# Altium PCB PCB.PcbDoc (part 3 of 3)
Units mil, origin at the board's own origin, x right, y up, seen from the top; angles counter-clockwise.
Board outline 5645.41 x 3720.47 mil, 4 copper layers (Top Layer, Signal Layer 1, Signal Layer 2, Bottom Layer), stack 61.2 mil thick; 253 components, 113 nets, 631 pads, 211 vias.
Unrouted connection lines stored in the file: 1.
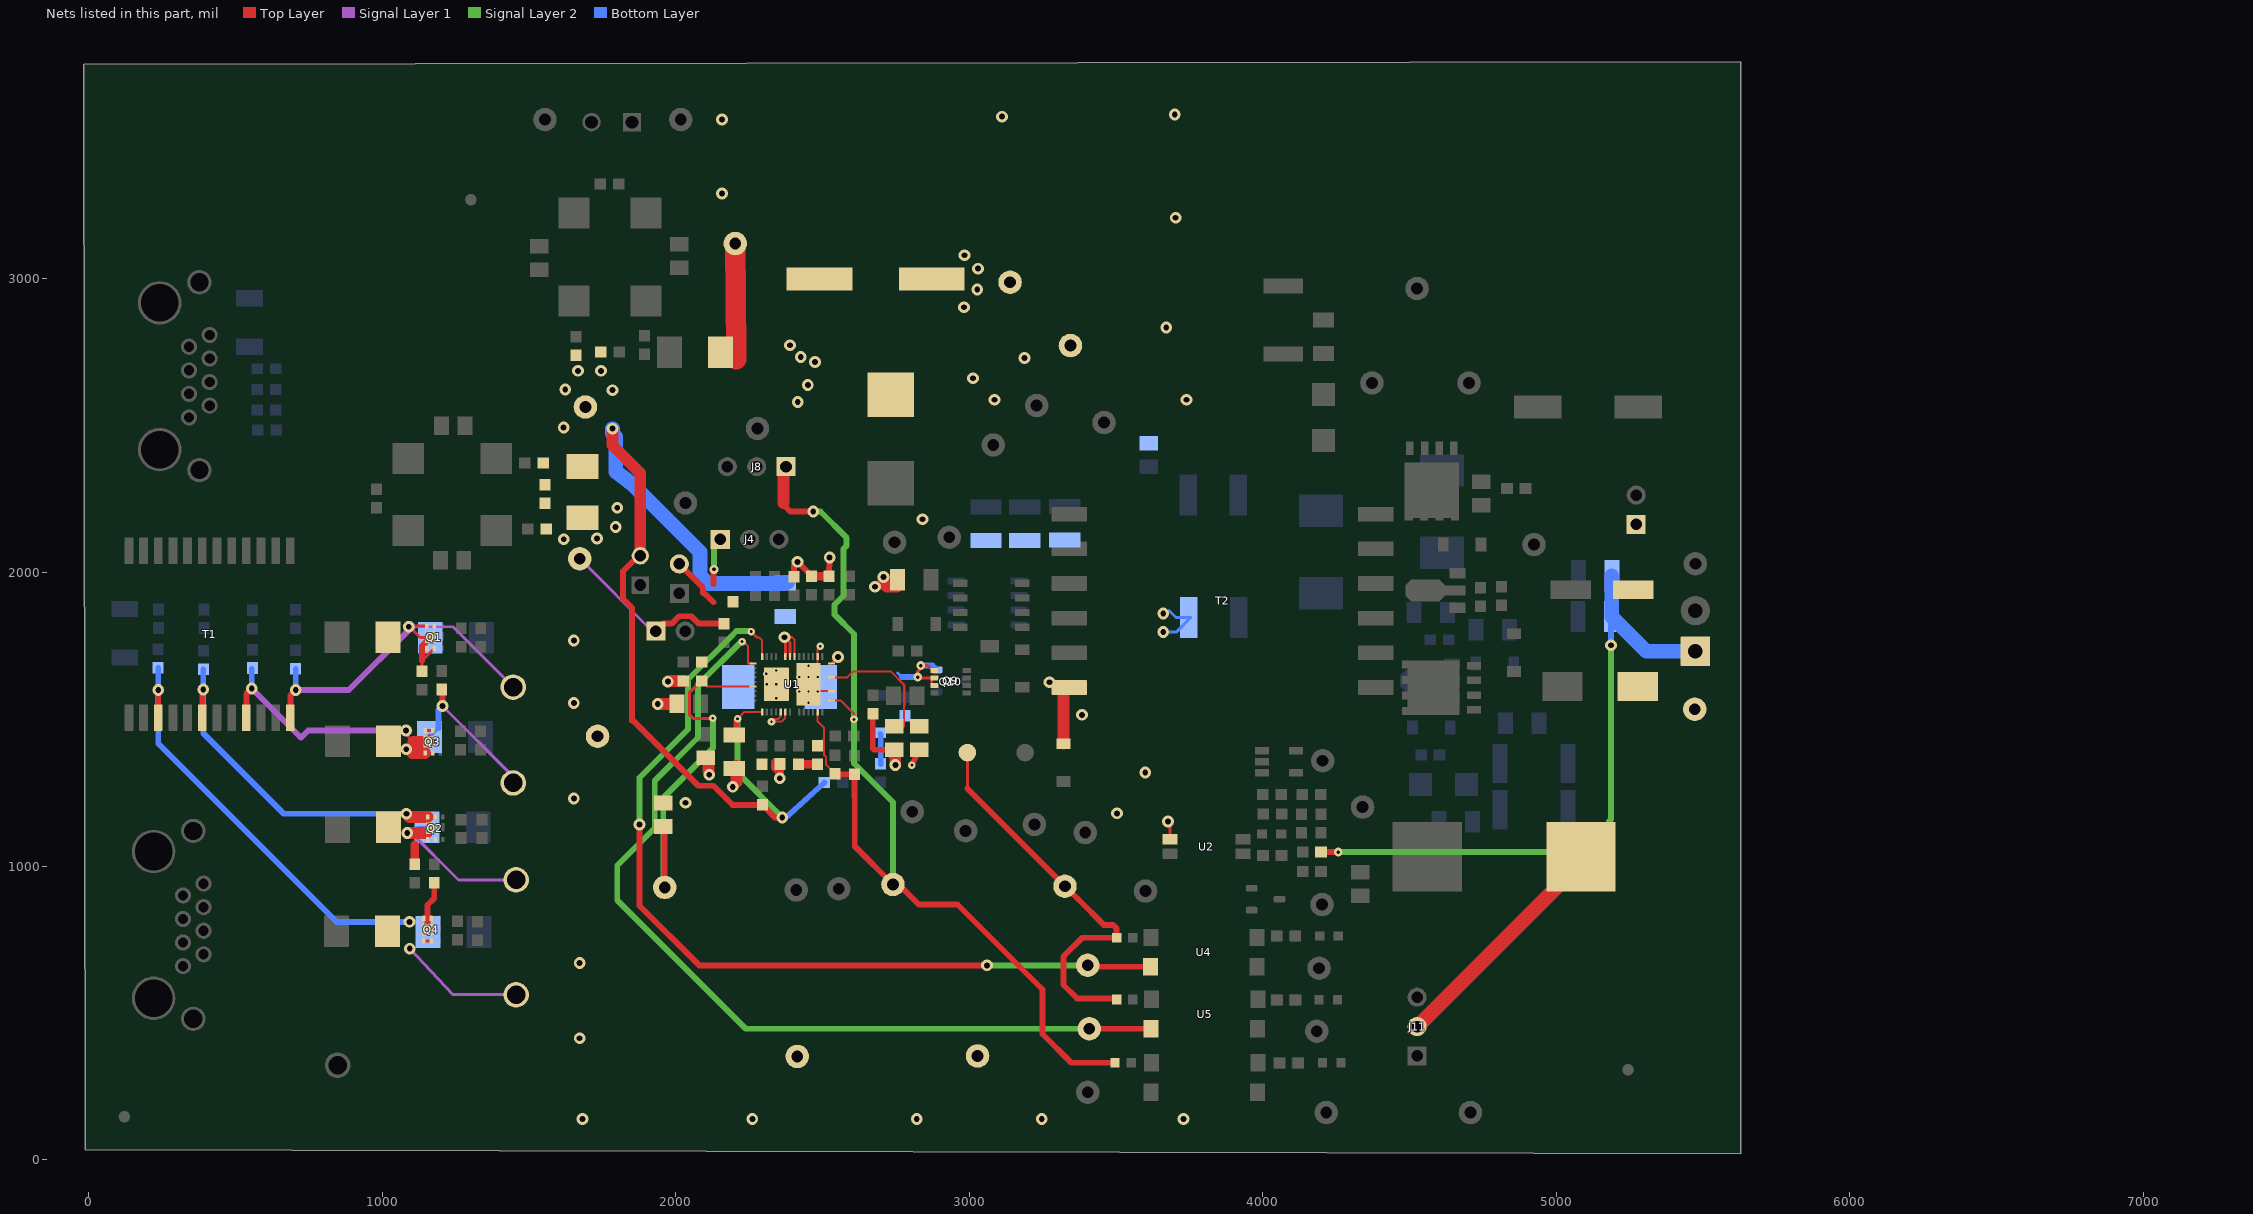
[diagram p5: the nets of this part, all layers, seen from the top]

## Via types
v1: diameter 40, hole 20, Top Layer to Bottom Layer, 113 vias
v2: diameter 40, hole 20, Top Layer to Bottom Layer, tented both sides, 29 vias
v3: diameter 40, hole 20, Top Layer to Bottom Layer, tented top, 15 vias
v4: diameter 19.68, hole 7.87, Top Layer to Bottom Layer, 13 vias
v5: diameter 26, hole 10, Top Layer to Bottom Layer, tented both sides, 11 vias
v6: diameter 40, hole 20, Top Layer to Bottom Layer, tented bottom, 10 vias
v7: diameter 30, hole 12, Top Layer to Bottom Layer, tented both sides, 6 vias
v8: diameter 30, hole 12, Top Layer to Bottom Layer, tented top, 5 vias
v9: diameter 26, hole 10, Top Layer to Bottom Layer, tented top, 3 vias
v10: diameter 26, hole 8, Top Layer to Bottom Layer, tented both sides, 2 vias
v11: diameter 20, hole 8, Top Layer to Bottom Layer, 1 vias
v12: diameter 26, hole 8, Top Layer to Bottom Layer, tented bottom, 1 vias
v13: diameter 26, hole 10, Top Layer to Bottom Layer, 1 vias
v14: diameter 30, hole 12, Top Layer to Bottom Layer, 1 vias

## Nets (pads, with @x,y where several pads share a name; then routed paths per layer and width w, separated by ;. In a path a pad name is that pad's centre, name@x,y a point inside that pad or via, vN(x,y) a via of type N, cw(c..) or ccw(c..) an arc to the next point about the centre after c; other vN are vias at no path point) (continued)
PGND: C8.2 C16.2 C20.2 C21.2 C22.2 C23.2 C24.2 C25.2 C32.2 C35.1 C38.2 C40.1 C41.2 C42.1 C46.2 D16.2 D20.1 D24.1 J4.1 J9.2 L3.2 Q9.2 Q10.1 Q10.2 Q10.3 R11.1 R26.1 R36.1 R37.1 R52.1 R54.1 R55.1 T2.6 TP29.1 TP35.1 TP39.1 TP42.1 U1.2 U1.7 U1.8 U1.9 U1.39 U1.45 U1.46 U2.3 | length 2558.2
  Top Layer w7: v3(2371.38,1779.4) 2396.36,1779.4 2405.4,1770.36 U1.7@2405.4,1713.66 ; U1.46@2476.27,1595.55 U1.39@2531.39,1595.55 ; U1.46@2484.14,1650.67 U1.2@2484.14,1713.66 2484.14,1739.8 v5(2493.02,1748.67) ; U1.45@2531.39,1690.04 v2(2553.37,1712.03)
  Top Layer w10: L3.2@1661.01,2740.76 L3.2@1667.86,2733.91 ; C8.2@1735.94,2740.76 C8.2@1745.79,2750.6 ; R54.1@2290.49,1332.27 2303.07,1344.85 R54.1@2302.39,1345.53 ; v3(2371.38,1779.4) v3@2373.91,1776.87 ; U1.9@2373.91,1713.66 v3@2373.91,1776.87 ; U1.8@2389.65,1713.66 2389.65,1761.12 v3@2373.91,1776.87 ; C35.1@2419.04,1346.41 C35.1@2419.45,1346.82 ; C41.2@2463.64,1987.19 C41.2@2463.64,1988.09 ; U1.46@2476.27,1595.55 U1.46@2452.65,1619.18 U1.46@2484.14,1650.67 ; C38.2@2725.55,1377.34 C38.2@2744.29,1396.08 C38.2@2744.29,1378.11 ; v7@2813.8,1640.83 v7@2829.48,1640.83 ; v7(2824.8,1643.7) v7@2824.8,1645.51 ; 2872.9,1630.99 2872.9,1617.47 Q10.3@2875.13,1615.24 ; Q10.1@2875.13,1666.42 2858.48,1683.07 v7(2835.66,1683.07) 2835.66,1674.03 2824.8,1663.16 v7@2824.8,1645.51 ; Q10.2@2881.89,1640.83 v7@2829.48,1640.83 ; T2.6@3318.26,1593.23 T2.6@3321.99,1589.5 ; v1(3677.55,1151.57) 3684.55,1144.58 U2.3@3684.55,1091.15 ; v7@2824.8,1645.51 v7@2829.48,1640.83
  Top Layer w20: J9.2@2012.89,2029.13 2092.52,1949.5 2092.52,1929.93 2096.93,1929.93 2102.99,1923.87 2103.66,1923.87 2129.1,1898.44 ; 2129.1,1961.43 2129.1,2008.52 v8(2130.92,2010.34) ; R37.1@2403.18,1985.08 2403.18,2023.88 v3(2415.51,2036.22) C41.2@2463.64,1988.09 ; C46.2@2523.35,1987.19 v3(2524.98,2051.39) v3@2524.98,2042.68 ; C42.1@2671.97,1518.37 2671.97,1401.09 2676.98,1396.08 C38.2@2744.29,1396.08 ; v5(2805.12,1343.46) C32.2@2830.91,1396.08
  Top Layer w30: R55.1@2340.44,1353.85 2340.44,1335.72 2354.97,1321.2 v2(2354.97,1299.21) ; C35.1@2419.45,1346.82 C40.1@2482.83,1346.82 ; C41.2@2463.64,1987.19 C46.2@2523.35,1987.19
  Top Layer w40: v3(2708.13,1984.44) 2708.13,1962.24 2719.32,1951.05 R52.1@2754.13,1951.05 ; C38.2@2744.29,1378.11 2748.71,1373.69 v2(2748.71,1344.07) ; D16.2@3321.99,1416.94 T2.6@3321.99,1589.5
  Signal Layer 2 w20: v8(2130.92,2010.34) 2130.92,2091.51 J4.1@2152.24,2112.84 J4.1@2151.5,2109.55
  Bottom Layer w10: D20.1@2693.4,1453.34 D20.1@2698.84,1447.89 ; 2756.74,1657.54 2770.58,1643.7 ; v1(3661.42,1797.38) 3706.1,1797.38 3707.18,1798.46 3755.31,1846.6 3704.95,1846.6 3680.71,1870.83 3670.12,1860.24 v1(3661.66,1860.24)
  Bottom Layer w20: R26.1@2698.84,1347.81 D20.1@2698.84,1447.89 ; 2770.58,1643.7 v7(2824.8,1643.7) ; v7(2835.66,1683.07) 2875.14,1683.07 Q9.2@2889.82,1668.39
  other v1: 1683.07,137.8 2261.56,137.8 2821.68,137.8 3247.51,137.8 3730.31,137.8 1673.23,413.39 1673.23,669.29 3600.14,1318.9 3384.99,1514.94 3273.86,1625.99 2841.22,2181.56 3740.46,2588.58 3013.69,2662.02 3188.98,2730.49 3671.86,2834.65 2982.28,2903.54 3027.62,2964.28 3030.49,3035.15 2984.05,3080.71 3703.86,3208.66 2158.54,3543.31 3112.49,3553.15 3700.79,3560.78
  other v2: 3086.46,2588.58 1667.86,2687.01 1745.79,2687.01 2158.54,3291.03
  other v3: 3503.94,1179.47
  other v4: 2452.65,1556.18 2420.95,1594.57 2452.65,1594.57 2484.34,1594.57 2420.95,1643.78 2452.65,1643.78 2484.34,1643.78 2452.65,1682.17
  other v6: 2679.76,1951.59
PPD: C11.1 R14.2 R19.2 TP10.1 U1.19 | length 1261.6
  Top Layer w7: R19.2@2089.03,1630.93 2108.66,1611.3 U1.19@2263.67,1611.3
  Top Layer w10: C11.1@1958.66,1134.89 C11.1@1962.89,1130.66 ; R19.2@2089.03,1630.93 2087.4,1630.93 2046.87,1590.41 2046.87,1516.74 2060.6,1503.02 v10(2127.09,1503.02)
  Top Layer w20: TP10.1@1962.89,927.16 C11.1@1962.89,1130.66
  Signal Layer 2 w20: TP10.1@1958.18,922.18 1958.18,1232.71 2127.09,1401.62 v10(2127.09,1503.02)
PR12: C1.2 D2.2 D7.1 Q1.1 Q1.2 Q1.5 Q1.6 Q1.8 R16.2 T1.24 TP1.1 | length 1490.4
  Top Layer w10: R16.2@1136.5,1663.89 1136.5,1699.47 Q1.2@1177.83,1740.81 ; 1136.5,1750.65 1142.4,1750.65 Q1.1@1152.24,1740.81 ; Q1.6@1152.24,1817.58 1104.76,1817.58 1102.37,1815.19 v2(1090.81,1815.19) 1093.38,1815.19 1129.37,1779.2 Q1.8@1165.04,1779.2
  Top Layer w20: T1.24@687.6,1504.68 687.6,1581.12 v1(705.84,1599.36) ; 1136.5,1699.47 1136.5,1750.65 Q1.8@1165.04,1779.2
  Signal Layer 1 w10: v2(1090.81,1815.19) 1241.2,1815.19 1245.69,1810.69 TP1.1@1446.85,1609.54
  Signal Layer 1 w20: v1(705.84,1599.36) 886.54,1599.36 1090.81,1803.63 v2(1090.81,1815.19)
  Bottom Layer w10: C1.2@705.58,1672.06 C1.2@705.84,1671.79 ; D7.1@1130.72,1777.85 D7.1@1164.14,1777.85
  Bottom Layer w20: v1(705.84,1599.36) C1.2@705.84,1671.79
  Bottom Layer w40: v2(1090.81,1815.19) v2@1093.38,1815.19
PR36: C2.2 D3.2 D8.1 Q3.1 Q3.2 Q3.5 Q3.6 Q3.8 R15.2 T1.21 TP2.1 | length 1572.9
  Top Layer w10: v6(1081.95,1461.51) 1081.95,1448.01 1106.64,1423.32 ; v6(1082.55,1397.64) 1090.61,1397.64 1103.31,1384.93 ; Q3.1@1147.12,1384.93 Q3.2@1172.71,1384.93 ; Q3.6@1147.12,1461.71 Q3.5@1172.71,1461.71 ; Q3.8@1159.92,1423.32 1159.92,1445.85 ; R15.2@1203.42,1601.45 R15.2@1205.82,1599.05
  Top Layer w20: T1.21@537.6,1504.68 537.6,1586.55 v1(556.1,1605.05) ; v2(1205.82,1545.28) R15.2@1205.82,1599.05
  Top Layer w40: 1103.31,1384.93 Q3.1@1147.12,1384.93 ; 1106.64,1423.32 Q3.8@1159.92,1423.32
  Signal Layer 1 w10: v2(1205.82,1545.28) 1446.85,1304.25 TP2.1@1446.85,1283.01
  Signal Layer 1 w20: v1(556.1,1605.05) 724.15,1437.01 748.65,1461.51 v6(1081.95,1461.51)
  Bottom Layer w10: C2.2@556.1,1671.61 C2.2@559.05,1674.56 ; D8.1@1162.14,1439.37 D8.1@1192.36,1469.59
  Bottom Layer w20: v1(556.1,1605.05) C2.2@556.1,1671.61 ; D8.1@1192.36,1469.59 1192.36,1531.81 v2(1205.82,1545.28)
PR45: C3.2 D4.2 D9.1 Q2.1 Q2.2 Q2.5 Q2.6 Q2.8 R18.2 T1.18 TP3.1 | length 1828.1
  Top Layer w10: v1@387.6,1598.17 v1(390.88,1601.45) ; v6(1082.68,1178) v6@1093.46,1167.22 ; Q2.8@1151.22,1112.2 Q2.8@1167.84,1128.83
  Top Layer w20: T1.18@387.6,1504.68 v1@387.6,1598.17
  Top Layer w30: R18.2@1111.38,1005.91 1111.38,1072.37
  Top Layer w40: v6(1086,1112.2) Q2.8@1151.22,1112.2 ; v6@1093.46,1167.22 Q2.6@1155.04,1167.22
  Signal Layer 1 w10: v6(1086,1112.2) 1091.84,1112.2 1096.37,1116.74 1260.36,952.76 TP3.1@1456.69,952.76
  Bottom Layer w10: C3.2@390.88,1669.79 C3.2@391.73,1670.64 ; D9.1@1120.49,1131.78 D9.1@1153.67,1131.78
  Bottom Layer w20: C3.2@390.88,1669.79 v1(390.88,1601.45) 390.88,1452.06 664.94,1178 v6(1082.68,1178)
PR78: C4.2 D5.2 D10.1 Q4.1 Q4.2 Q4.5 Q4.6 Q4.8 R17.2 T1.15 TP4.1 | length 2139.8
  Top Layer w10: v6(1094.4,718.5) v6@1094.4,725.68 ; Q4.1@1141.73,744.93 Q4.2@1167.32,744.93 ; Q4.6@1141.73,821.7 1154.53,821.7 Q4.5@1167.32,821.7
  Top Layer w20: T1.15@237.6,1504.68 v1(237.6,1599.36) ; Q4.8@1154.53,783.32 1154.53,821.7 1154.53,867.02 1177.83,890.33 R17.2@1177.83,943.74
  Signal Layer 1 w10: v6@1091.48,711.94 v6@1094.4,709.03 ; v6@1094.4,723.51 v6@1094.4,709.03 ; TP4.1@1437.01,562.69 1240.73,562.69 v6(1094.4,718.5) v6@1094.4,709.03
  Bottom Layer w10: C4.2@236.43,1675.6 C4.2@237.6,1674.43 ; v6@1086.15,806.96 1088.87,809.68 v6(1093.35,809.68) 1089.62,809.68 v6@1089.25,810.05
  Bottom Layer w20: C4.2@237.6,1674.43 v1(237.6,1599.36) 237.6,1417.66 844.83,810.43 845.57,809.68 v6(1093.35,809.68)
TPH: TP44.1 U1.13 U4.2 | length 3055.7
  Top Layer w7: v5(2257.76,1798.46) 2277.58,1778.65 2285.09,1778.65 2295.17,1768.57 U1.13@2295.17,1713.66
  Top Layer w10: TP44.1@3404.21,661.49 TP44.1@3409.01,656.69
  Top Layer w20: v1(1877.39,1141.73) 1877.39,864.74 2080.64,661.49 v1(3061.02,661.49) ; TP44.1@3409.01,656.69 U4.2@3618.54,656.69
  Signal Layer 2 w10: v1(3061.02,661.49) v1@3073.47,661.49
  Signal Layer 2 w20: v1(1877.39,1141.73) 1877.39,1300.55 2042.67,1465.84 2042.67,1635.72 2187.53,1780.57 2207.52,1800.55 2255.67,1800.55 v5(2257.76,1798.46) ; v1@3073.47,661.49 TP44.1@3404.21,661.49
TPL: TP46.1 U1.14 U5.2 | length 3162.9
  Top Layer w7: v5(2226.83,1764.44) 2231.61,1764.44 2246.08,1749.97 2246.08,1690.04 U1.14@2263.67,1690.04
  Top Layer w20: TP46.1@3409.85,445.54 U5.2@3620.53,445.54
  Signal Layer 2 w20: v5(2226.83,1764.44) 2223.34,1764.44 2076.77,1617.88 2076.77,1438.14 1929.13,1290.5 1929.13,1129.43 1801.18,1001.47 1801.18,883.32 2238.96,445.54 TP46.1@3409.85,445.54
VB: C40.2 J8.1 R43.2 R46.2 R64.2 TP33.1 U1.34 U1.37 | length 3644.7
  Top Layer w7: C40.2@2482.83,1409.81 2505.64,1432.62 ; U1.34@2484.14,1524.69 2484.14,1492.23 2505.64,1470.73 2505.64,1432.62 ; U1.37@2531.39,1564.06 2562.84,1564.06 2607.96,1518.93 v13(2607.96,1499.75) ; R46.2@2543.68,1314.08 2512.91,1344.85 2512.91,1371.21 2505.64,1378.48 2505.64,1432.62
  Top Layer w10: 2361.56,2236.51 2367.51,2236.51 ; C40.2@2480.31,1409.81 C40.2@2482.83,1409.81 ; R46.2@2543.68,1314.08 R46.2@2545.19,1312.57
  Top Layer w20: 2361.56,2236.51 2390.55,2207.52 ; 2390.57,2207.54 v3(2469.13,2207.54) ; R46.2@2545.19,1312.57 R43.2@2610.05,1312.57 2610.55,1150.17 2610.55,1067.22 TP33.1@2740.65,937.12 ; TP33.1@2750.43,946.9 2828.65,868.68 2960.63,868.68 3250.12,579.18 3250.12,428.01 3348.57,329.56 R64.2@3497.5,329.56
  Top Layer w40: 2367.51,2236.51 J8.1@2367.51,2352.03
  Signal Layer 2 w20: v3(2469.13,2207.54) 2493.46,2207.54 2582.85,2118.15 2582.85,2091.57 2572.22,2080.94 2572.22,1920.62 2541.35,1889.75 2541.35,1864.17 2542.05,1863.47 2542.05,1856.23 2607.96,1790.32 v13(2607.96,1499.75) 2607.96,1349.8 2740.65,1217.11 TP33.1@2740.65,937.12
VCC: C32.1 C38.1 L9.1 R62.2 R63.2 TP24.1 U1.42 | length 1815.6
  Top Layer w7: U1.42@2531.39,1642.8 2584.93,1642.8 2605.22,1663.1 2732.8,1663.1 2779.05,1616.85 2779.05,1544.42 2778.35,1543.72 2778.35,1476.08 C38.1@2744.29,1476.08
  Top Layer w10: 2994.22,1264.39 L9.1@2994.22,1386.08
  Top Layer w20: 2994.22,1264.39 3301.39,956.51 TP24.1@3326.77,931.13 3370.79,887.29 3458.82,799.61 3490.23,799.61 3502.84,787 R62.2@3502.84,755.76 3385.52,755.76 3321.99,692.24 3321.99,594.7 3368.06,548.63 3499.75,548.63 R63.2@3502.84,545.54
VDD: C10.1 C20.1 C21.1 C34.1 D1.1 D6.1 J5.2 L4.2 L7.1 R25.2 R51.1 TP9.1 TP13.1 U1.23 | length 3873.4
  Top Layer w7: v5@2207.45,1497.86 v5(2211.35,1501.77) 2234.27,1524.69 U1.23@2295.17,1524.69
  Top Layer w10: D1.1@2153.79,2750.6 2203.42,2800.24
  Top Layer w20: J5.2@1879.92,2063.29 1820.77,2004.13 1820.77,1910.19 1852.05,1878.91 1852.05,1494.7 1856.24,1494.7 2077.68,1273.26 2128.91,1273.26 2193.91,1208.26 R51.1@2296.06,1208.26 2337.8,1166.52 2337.8,1165.19 v3(2363.61,1165.19) ; C34.1@2207.45,1444.73 v5@2207.45,1497.86 ; R51.1@2296.06,1211.7 R51.1@2296.06,1208.26
  Top Layer w40: v1(1785.09,2490.16) 1785.09,2433.53 1879.92,2338.71 J5.2@1879.92,2063.29
  Top Layer w70: TP9.1@2203.42,3120.73 2206.35,2751.02 2206.54,2726.38
  Signal Layer 2 w20: v5(2211.35,1501.77) 2211.35,1317.45 v3(2363.61,1165.19)
  Bottom Layer w20: v3@2369.01,1159.25 R25.2@2507.02,1284.56
  Bottom Layer w50: v1(1785.09,2490.16) 1785.09,2474.12 1796.53,2462.68 1796.53,2344.3 1854.06,2299.57 2017.21,2135.83 2083.04,2070 2083.04,1990.51 2111.09,1962.46 2370.91,1962.46 2374.77,1966.32 2381.44,1966.34 2374.77,1966.42 C20.1@2373.93,1966.43
  other v1: 1618.73,2493.77 2416.32,2580.74 1624.02,2623.29 2450.79,2638.62 2475.09,2717.39 2389.77,2774.34
  other v2: 1785.47,2621.34 2426.29,2733.91
VOUT: C27.2 C28.1 C29.2 J6.1 J7.1 J11.2 L8.2 R39.2 TP14.1 | length 3029.2
  Top Layer w10: L8.2@5085.08,1011.88 L8.2@5085.08,1032.05
  Top Layer w20: R39.2@4199.07,1047.45 v7(4257.43,1047.45)
  Top Layer w50: J11.2@4526.26,453.06 L8.2@5085.08,1011.88
  Signal Layer 2 w20: v7(4257.43,1047.45) 5094.82,1047.45 5189.1,1141.73 5179.25,1151.57 5187,1159.32 v2(5187,1751.97)
  Bottom Layer w10: C29.2@5187,1847.86 C29.2@5189.1,1849.96
  Bottom Layer w20: v2(5187,1751.97) C29.2@5187,1847.86
  Bottom Layer w50: C27.2@5189.1,1988.9 C29.2@5189.1,1849.96 5307.09,1731.97 J6.1@5474.53,1731.97
VSS: C10.2 C11.2 C34.2 D6.2 D24.2 J10.1 L6.2 R19.1 R40.1 R47.1 R49.1 TP11.1 TP38.1 U1.27 U1.28 U1.47 | length 980.2
  Top Layer w7: v12(2326.77,1491.14) v12@2333.84,1491.14 ; U1.27@2359.22,1524.69 2357.72,1523.19 2357.72,1509.32 2349.91,1501.5 2334.86,1501.5 2334.86,1491.85 v12@2334.71,1491.69 ; U1.28@2372.84,1524.69 2372.84,1503.38 2361.31,1491.85 2340.12,1491.85 2337.33,1489.07 v12@2334.71,1491.69 ; v12@2333.84,1491.14 2334.15,1491.14 v12@2334.71,1491.69 ; v12@2333.84,1491.14 2334.55,1491.85 v12@2334.71,1491.69
  Top Layer w10: v2(1973.68,1628.05) v2@1975.62,1629.98 ; v3@2112.1,1324.39 2114.61,1321.87 v3(2114.61,1311.13) ; v2(2194.88,1269.68) 2201.94,1269.68 v2@2207.95,1275.69
  Top Layer w20: J10.1@1932.68,1800.55 1957.77,1825.64 1986.55,1825.64 2011.82,1850.91 2053.54,1850.91 2078.81,1825.64 R40.1@2165.79,1825.64
  Top Layer w40: v1(1939.22,1552.39) 1979.95,1552.39 R49.1@1982.38,1554.82 ; v2@1975.62,1629.98 R19.1@2026.88,1629.98 ; v3@2112.1,1324.39 R47.1@2112.1,1368.37 ; 2207.45,1286.02 C34.2@2207.45,1340.38
  Signal Layer 1 w10: TP11.1@1673.23,2047.24 1919.92,1800.55 J10.1@1932.68,1800.55
  other v1: 2033.74,1215.5 1653.54,1230.32 1653.54,1555.55 1653.54,1768.57 1618.98,2113.16 1732.28,2116.14 1795.98,2155.02 1801.18,2220.73
  other v4: 2343.39,1571.93 2310.91,1619.18 2343.39,1619.18 2375.88,1619.18 2343.39,1666.42
  other v11: 2308.68,1654.51
pads on no net: FID1.1 FID2.1 FID3.1 H1.0 H2.0 H3.0 H4.0 LBL1.0 Q1.0 Q2.0 Q3.0 Q4.0 Q8.9@4521.67,2259.01 Q8.9@4521.67,2329.09 Q8.9@4578.76,2259.01 Q8.9@4578.76,2292.47 Q8.9@4578.76,2329.09 Q8.9@4635.84,2259.01 Q8.9@4635.84,2329.09 SH-J1.0 SH-J2.0 SH-J3.0 SH-J4.0 SH-J5.0 SH-J6.0 SH-J7.0 U1.6 U1.10 U1.15 U1.16 U1.22 U1.25 U1.26 U1.29 U1.30 U1.36 U1.44 U3.1 U3.2
copper on no net: | length 159.4
  Top Layer w7: 2288.74,1464.69 2368.03,1464.69 2374.8,1471.46 2421.15,1524.69

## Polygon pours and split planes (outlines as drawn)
VSS on Bottom Layer "BOTTOM_LAYER_VSS_P006" (solid, remove dead copper, pour order 6): 1599.53,2254.44 1599.53,1188.74 2245.32,1188.74 2245.32,1374.46 2380.4,1509.55 2380.4,1719.41 2377.64,1722.17 2117.51,1722.17 2117.51,1849.85 1829.39,1849.85 1829.39,2249.31 1824.77,2253.94 1594.49,2253.94
PGND on Bottom Layer "BOTTOM_LAYER_PGND_P030" (solid, remove dead copper, pour order 30): 2084.75,3641.73 2091.34,3635.13 2091.35,2764.49 3779.53,2764.49 3779.53,3641.73 2091.34,3641.73
PGND on Bottom Layer "BOTTOM_LAYER_PGND_P024" (solid, remove dead copper, pour order 24): 1601.07,2772.25 1601.07,59.76 3778.82,59.76 3779.53,59.06 3779.53,2772.25
GND on Bottom Layer "BOTTOM_LAYER_GND_P017" (solid, remove dead copper, pour order 17): 3882.29,3641.73 3882.29,67.04 5569.75,67.04 5559.53,77.26 5559.53,3641.73
EARTH on Bottom Layer "BOTTOM_LAYER_EARTH_P016" (solid, remove dead copper, pour order 16): 19.68,255.13 34.02,3120.08 1227.16,3120.08 1231.97,3115.27 1231.97,1960.53 1326.37,1960.53 1383.26,1903.64 1383.26,1684.85 1519.17,1684.85 1530.51,1673.51 1530.51,47.58 19.68,53.86
EARTH on Bottom Layer "BOTTOM_LAYER_EARTH_P013" (solid, remove dead copper, pour order 13): 1227.16,618.95 1325.7,618.95 1387.8,681.04 1387.8,1668.59 1522.13,1668.59 1535.43,1681.9 1535.43,58.34 1227.16,58.34 1217.16,68.34 1217.16,619.92
no net on Bottom Layer "BOTTOM_LAYER_NONET_P009" (solid, remove dead copper, pour order 9): 108.96,2754.48
VSS on Top Layer "TOP_LAYER_VSS_P007" (solid, remove dead copper, pour order 7): 1537.94,2244.22 1547.42,2234.74 1547.42,2118.15 1589.54,2118.15 1603.22,2104.48 1603.22,1186.64 2246.69,1186.64 2246.69,1457.24 2331.52,1457.24 2387.27,1512.99 2387.27,1717.31 2140.51,1717.31 2117.93,1739.89 2117.93,1860.59 1834.91,1860.59 1832.07,1857.75 1829.46,1860.36 1829.46,2251.8 1551.23,2251.8 1550.2,2250.77
no net on Top Layer "TOP_LAYER_NONET_P032" (solid, remove dead copper, pour order 32): 1604.57,2234.25 1611.07,2227.75 1611.07,1199.4
no net on Top Layer "TOP_LAYER_NONET_P031" (solid, remove dead copper, pour order 31): 935.56,1241.94
PGND on Top Layer "TOP_LAYER_PGND_P027" (solid, remove dead copper, pour order 27): 2091.34,3641.73 2098.96,2401.8 3779.53,2401.8 3779.53,3641.73
PGND on Top Layer "TOP_LAYER_PGND_P025" (solid, remove dead copper, pour order 25): 1604.57,2774.34 1604.57,50.5 3778.24,50.5 3779.53,49.21 3779.53,2774.34
VSS on Top Layer "TOP_LAYER_VSS_P022" (solid, remove dead copper, pour order 22): 1535.79,2246.32 1545.28,2236.84 1545.28,2120.25 1587.4,2120.25 1601.07,2106.58 1601.07,1188.74 2244.54,1188.74 2244.54,1459.34 2329.37,1459.34 2385.13,1515.09 2385.13,1719.41 2138.36,1719.41 2115.79,1741.99 2115.79,1862.69 1832.76,1862.69 1829.92,1859.85 1827.31,1862.46 1827.31,2253.9 1549.08,2253.9 1548.05,2252.87
GND on Top Layer "TOP_LAYER_GND_P020" (solid, remove dead copper, pour order 20): 3877.95,1830.27 3877.95,67.04 5561.02,67.04 5561.02,868.68 4423.55,868.68 4397.39,894.84 4397.39,1712.37 4279.48,1830.27
GND on Top Layer "TOP_LAYER_GND_P019" (solid, remove dead copper, pour order 19): 3877.95,3640.32 3877.95,1830.27 5561.02,1830.27 5561.02,3640.32
EARTH on Top Layer "TOP_LAYER_EARTH_P015" (solid, remove dead copper, pour order 15): 29.53,3120.08 1227.16,3120.08 1227.16,1955.16 1223.11,1951.11 1245.43,1928.79 1340.53,1928.79 1340.53,1715.86 1366.12,1690.26 1535.43,1690.26 1535.43,62.65 1526.48,53.7 22.04,53.7 22.04,3112.59
no net on Top Layer "TOP_LAYER_NONET_P011" (solid, remove dead copper, pour order 11): 1241.31,2849.25
no net on Top Layer "TOP_LAYER_NONET_P010" (solid, remove dead copper, pour order 10): 1238.86,2362.2
VSS on Signal Layer 2 "SIGNAL_LAYER_2_VSS_P005" (solid, remove dead copper, pour order 5): 1599.53,2251.82 1599.53,1190.29 1601.07,1188.74 2253.9,1188.74 2253.9,1371.11 2247.93,1377.08 2386.2,1515.35 2386.2,1713.61 2380.4,1719.41 2134.94,1719.41 2134.94,1852.86 2131.93,1849.85 1829.39,1849.85 1829.39,2251.82
PGND on Signal Layer 2 "SIGNAL_LAYER_2_PGND_P029" (solid, remove dead copper, pour order 29): 2096.46,3639.42 2096.46,2509.34 3776.02,2509.34 3779.37,2505.99 3779.53,3639.42
PGND on Signal Layer 2 "SIGNAL_LAYER_2_PGND_P026" (solid, remove dead copper, pour order 26): 1601.07,2756.7 1601.07,59.76 3768.98,59.76 3789.98,38.76 3779.37,2756.7
GND on Signal Layer 2 "SIGNAL_LAYER_2_GND_P021" (solid, remove dead copper, pour order 21): 3882.29,3640.32 3882.29,67.04 5559.53,67.04 5559.53,3640.32
EARTH on Signal Layer 2 "SIGNAL_LAYER_2_EARTH_P012" (solid, remove dead copper, pour order 12): 29.53,3120.08 1227.16,3120.08 1227.16,1928.79 1216.97,1918.6 1224.45,1911.13 1383.26,1911.13 1383.26,1691.47 1535.43,1691.47 1535.43,54.99 1532.92,53.7 1491.58,53.7 18.62,53.7 34.02,3120.08
VSS on Signal Layer 1 "SIGNAL_LAYER_1_VSS_P004" (solid, remove dead copper, pour order 4): 1604.57,2244.09 1601.07,2240.6 1601.07,1188.74 2238.21,1188.74 2241.72,1185.23 2244.09,1187.61 2244.09,1369.33 2385.13,1510.36 2385.13,1671.96 2381.19,1675.89 2127.79,1675.89 2127.79,1852.06 2125.28,1854.57 2120.56,1849.85 1829.39,1849.85 1829.39,2251.82 1827.28,2253.94 1594.49,2253.94
PGND on Signal Layer 1 "SIGNAL_LAYER_1_PGND_P028" (solid, remove dead copper, pour order 28): 2091.34,3641.73 2091.34,2769.19 3774.83,2769.19 3779.53,2764.49 3779.53,3641.73
PGND on Signal Layer 1 "SIGNAL_LAYER_1_PGND_P023" (solid, remove dead copper, pour order 23): 1604.57,2772.25 1604.57,3552.91 1604.57,49.21 3779.53,49.21 3779.53,2772.25
GND on Signal Layer 1 "SIGNAL_LAYER_1_GND_P018" (solid, remove dead copper, pour order 18): 3869.09,3641.45 3869.09,54.06 5559.53,54.06 5559.53,3641.45
EARTH on Signal Layer 1 "SIGNAL_LAYER_1_EARTH_P014" (solid, remove dead copper, pour order 14): 34.02,3120.08 1230.32,3120.08 1230.32,1919.6 1334.04,1919.6 1348.05,1905.6 1348.05,1691.78 1515.68,1691.78 1535.43,1672.03 1535.43,59.76 1541.5,53.7 20.47,53.7

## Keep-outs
Keep-Out Layer:
  text ".Layer_Name" at 577,-858.49 h60

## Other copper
Top Layer:
  rectangle net NetD23_2: 4046,963.34 4157.88,1134.42
  rectangle net NetC31_1: 4168.07,2224.41 4450.73,2488.84
  rectangle net NetC31_1: 4594.1,2192.87 4778.56,2263.78
  rectangle net NetC31_1: 4621.55,2073.47 4674.11,2376.23
  rectangle net PGND: 1601.07,2667.48 1771.65,2772.25
  rectangle net PGND: 2866.8,1607.36 2894.45,1674.75
  rectangle net VB: 2464.13,1387.8 2506.48,1429.3
  rectangle net GND: 4539.57,2398.97 4668.07,2448.18
  rectangle: 2272.24,1449.77 2298.54,1473.56
  rectangle net NetL1_1: 1840.55,2785.43 1923.94,3065.38
  rectangle net GND: 4696.28,1515.75 4951.15,1646.97
  rectangle net NetC9_1: 807.06,712.76 925.2,2533.2
  rectangle net NetL1_1: 1840.55,2836.82 2046.48,3067.42
  rectangle net NetL2_4: 1499.55,2806.25 1761.57,3058.54
  rectangle net NetC7_1: 1785.09,3089.07 2047.24,3641.73
  rectangle net NetC7_2: 1505.91,3090.55 1761.81,3641.73
  rectangle net PR45: 935.56,984.25 1130.08,1241.94
  rectangle net NetC31_1: 4537.4,2175.2 4669.23,2197.42
  rectangle net VDD: 2102.69,2599.31 2420.17,2806.01
  rectangle net VDD: 2317.05,2536.9 2489.3,2800.46
  rectangle net VDD: 1601.07,2539.37 2794.14,2654.2
  rectangle net VDD: 1595.04,2293.31 1868.74,2627.95
  rectangle net VDD: 2318.43,2689.69 2646.97,3036.68
  rectangle net NetC8_1: 1791.34,2696.41 2027.56,2769.3
  rectangle net VSS: 1601.07,1908.06 1761.59,2254.6
  rectangle net NetQ11_1: 2885.87,1873.4 2984.5,1931.67
  rectangle net GND: 4914.97,1547.81 5095.32,1705.29
  rectangle net GND: 4976.74,1559.33 5157.48,2045.69
  rectangle net GND: 4803.58,2443.48 5024.02,2660.01
  rectangle net VOUT: 4969.85,917.89 5551.18,1532.97
  rectangle net VOUT: 5179.25,1489.1 5369.53,2196.02
  rectangle net VOUT: 5224.53,1487.3 5551.18,1793.87
  rectangle net NetC19_2: 4441.38,917.89 4678.75,1711.34
  rectangle net NetC19_2: 4146.2,1475.32 4615.33,1863.93
  rectangle net NetC31_1: 4327.6,1935.75 4628.45,2373.57
  rectangle net NetC18_2: 3375.98,2273.04 3714.97,2358.2
  rectangle net NetC18_2: 3369.69,2197.42 3714.97,2277.87
  rectangle net VCC: 2713.84,1449.77 3049.98,1518.28
  rectangle net VDD: 2332.38,2826.04 2651.77,3043.87
  region net VDD: 2686.34,3045.98 2479.64,3045.98 2479.64,2529.47 2686.34,2529.47
  rectangle net VDD: 1535.43,2286.22 1761.81,2392.27
  rectangle net PGND: 2722.95,1367.23 2858.47,1407.48
  rectangle net PGND: 2290.37,1324.25 2438.59,1364.96
  rectangle net NetQ11_1: 2846.68,1930.51 2995.67,1986.49
  rectangle net NetQ11_1: 2944.86,1854.12 2994.22,1971.58
  rectangle net NetC33_1: 3029.65,1803.72 3379.19,2003.41
  rectangle net NetC18_2: 3249.7,2039.94 3380.32,2295.84
  rectangle net NetC18_2: 2973.23,2169.81 3379.19,2305.68
  rectangle net NetC18_2: 2655.74,2224.41 2975.31,2382.36
  rectangle net NetC33_2: 2914.5,1577.34 3104.73,1674.69
  rectangle net NetR34_2: 2317.05,1903.81 2420.17,1941.51
  rectangle net CS: 2504.07,1905.18 2614.27,1943.38
  rectangle net PPD: 2071.27,1614.94 2109.98,1713.6
  rectangle net VSS: 1535.77,2104.63 1767.66,2253.94
  rectangle net NetC9_2: 962.3,2048.39 1180.2,2244.09
  rectangle net NetC9_1: 871.4,2263.78 1044.42,2381.89
  rectangle net NetC9_1: 903.39,2336.29 1229.46,2533.2
  rectangle net NetL5_4: 1250,2009.39 1514.36,2200.73
  rectangle net NetL4_1: 1259.84,2332.92 1505.23,2554.39
  rectangle net NetL4_1: 1335.31,2336.29 1505.23,2447
  rectangle net NetL5_4: 1336.15,2090.02 1515.75,2200.73
  rectangle net NetC15_1: 1186.54,649.61 1230.32,760.23
  region net PR12: 1184.72,1692.91 1184.72,1899.63 946.54,1899.63 946.54,1692.91
  region net PR36: 1181.1,1336.69 1181.1,1506.14 944.88,1506.14 944.88,1336.69
  region net PR45: 1189.9,1082.68 1189.9,1241.94 935.56,1241.94 935.56,1082.68
  region net PR78: 1176.11,688.87 1176.11,846.96 964.57,846.96 964.57,688.87
  region net NetC9_2: 1357.96,1777.85 1357.96,1833.07 1197.82,1833.07 1197.82,1777.85
  region net NetC9_2: 1358.63,1126.86 1358.63,1181 1198.36,1181 1198.36,1126.86
  region net NetC9_2: 1358.54,1426.88 1358.54,1488.6 1192.36,1488.6 1192.36,1426.88
  region net NetC9_2: 1344.35,784.64 1344.35,833.91 1186.54,833.91 1186.54,784.64
  region net NetC12_1: 1355.63,1722.48 1355.63,1756.79 1197.82,1756.79 1197.82,1722.48
  region net NetC13_1: 1350.17,1368.15 1350.17,1402.46 1192.36,1402.46 1192.36,1368.15
  region net NetC14_1: 1356.47,1070.4 1356.47,1104.72 1198.66,1104.72 1198.66,1070.4
  region net NetC15_1: 1344.36,725.92 1344.36,760.23 1186.54,760.23 1186.54,725.92
  text ".Layer_Name" at 577,-858.49 h60
Signal Layer 1:
  rectangle net NetC7_1: 1785.09,3090.55 2047.1,3641.73
  rectangle net NetL1_1: 1840.55,2839.18 2048.73,3070.87
  rectangle net NetL2_4: 1499.55,2806.25 1761.57,3061.9
  rectangle net NetC7_2: 1506.89,3090.55 1761.81,3641.73
  rectangle net NetC19_2: 4121.26,1458.56 4582.26,1878.41
Signal Layer 2:
  rectangle net NetL2_4: 1496.66,2806.25 1761.57,3061.9
  rectangle net NetL1_1: 1839.78,2836.82 2047.1,3067.42
  rectangle net NetC7_1: 1785.09,3090.11 2046.48,3641.73
  rectangle net NetC7_2: 1506.89,3090.55 1761.81,3641.73
  rectangle net GND: 5177.17,1808.56 5551.18,2094.3
  rectangle net VDD: 1605.28,2444.35 1830.48,2641.99
  rectangle net VDD: 1613.57,2539.37 2445.96,2654.2
  rectangle net VDD: 2322.16,2524.86 2651.98,3047.35
  rectangle net NetC31_1: 4121.26,1903.9 4696.28,2263.19
Bottom Layer:
  rectangle net NetC19_2: 4124.02,1646.97 4332.15,1982.17
  rectangle net NetC31_1: 4344.26,2006.36 4695.45,2161.94
  rectangle net PR12: 1076.67,1727.8 1210.63,1844.23
  rectangle net PR36: 1059.72,1378.04 1205.3,1496.06
  rectangle net PR45: 1051.14,1078.36 1195.55,1205.19
  rectangle net PR78: 1057.02,718.5 1192.91,840.44
  rectangle net NetL4_1: 1259.84,2336.29 1500.81,2554.39
  rectangle net NetL5_4: 1250,2010.37 1514.36,2200.73
  rectangle net NetC7_1: 1785.09,3090.55 2043.36,3641.73
  rectangle net NetL1_1: 1839.78,2839.18 2046.48,3061.02
  rectangle net NetL2_4: 1493.7,2806.25 1761.57,3058.54
  rectangle net NetC7_2: 1506.89,3090.55 1761.81,3639.42
  rectangle net NetC18_2: 2991.33,2194.88 3783.87,2303.15
  rectangle net NetC18_2: 3572.92,2333.59 3769.69,2394.27
  rectangle net VDD: 1595.04,2428.74 1832.52,2641.99
  rectangle net NetC33_1: 3141.45,1811.48 3248.03,1993.04
  rectangle net NetQ11_1: 2927.57,1807.8 2984.5,1931.67
  rectangle net NetC26_1: 4616.14,1673.23 4748.43,1899.31
  rectangle net NetC19_2: 4399.08,1448.36 4590.95,1903.9
  rectangle net NetC18_2: 3563.17,2197.45 3783.87,2394.27
  rectangle net NetC39_1: 2669.81,1540.63 2912.46,1603.54
  rectangle net NetC9_2: 1298.45,744.93 1365.07,1919.6
  rectangle net NetC6_2: 549.21,2458.29 597.68,2788.13
  rectangle net NetC6_2: 501.04,2740.76 595.53,2797.14
  text ".Layer_Name" at 577,-858.49 h60

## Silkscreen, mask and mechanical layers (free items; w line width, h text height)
Top Overlay:
  lines w10: 1998.03,1447.73 2050.41,1500.11 2256.67,1500.11 2266.41,1489.89 ; 2660.51,1655.54 2673.81,1655.54 2701,1628.34 ; 3238.22,1557.26 3267.72,1527.77 3267.72,1526.24 3267.72,1269.92 3267.72,1213.94 3267.89,1213.77 3377.07,1213.77 ; 3865.55,1425.27 4149.11,1425.27 4166.96,1407.42 ; 4295.91,1026.13 4311.8,1026.13
  text "'.TID   .PCB_Rev" at 4494.1,3238.19 h108.27
  text "Test PG" at 1811.02,1397.64 h72.83
  text ".Layer_Name" at 577,-858.49 h60
Bottom Overlay:
  text ".Layer_Name" at 577,-858.49 h60
Top Paste:
  text ".Layer_Name" at 577,-858.49 h60
Bottom Paste:
  text ".Layer_Name" at 577,-858.49 h60
Top Solder:
  text ".Layer_Name" at 577,-858.49 h60
  text ".Layer_Name" at 577,-858.49 h60
Bottom Solder:
  text ".Layer_Name" at 577,-858.49 h60
Drill Guide:
  text ".Layer_Name" at 577,-858.49 h60
M1 Board Outline:
  lines w10: 5629.06,3740.16 5629.06,19.68 -14.47,33.27 -20.11,3730.4 5630.08,3738.56
  text ".Layer_Name" at 577,-858.49 h60
M2 Board Dimensions:
  rectangle: 0,-275 125,-150
  rectangle: 125,-400 500,-275
  lines w7: 0,-275 1000,-275 ; 125,-400 125,-150 ; 250,-400 250,-150 ; 500,-400 500,-150 ; 750,-400 750,-150 ; 0,-400 1000,-400 1000,-150 0,-150 0,-400
  text ".Layer_Name" at 577,-858.49 h60
M3 3D STEP Top:
  text ".Layer_Name" at 577,-858.49 h60
M4 3D STEP Bottom:
  text ".Layer_Name" at 577,-858.49 h60
M5 Assembly Top:
  lines w10: -292,-930.17 6308,-930.17 ; -292,-726.83 6310,-726.83 ; -292,-523.5 -292,-1133.5 3713,-1133.5 6310,-1133.5 6310,-523.5 -291.5,-523.5 -291.5,-1133.5 1284,-1133.5 ; 2173,-1133.5 2173,-523.5 ; 3440,-726.83 3440,-523.5 ; 4280,-726.83 4280,-523.5 ; 4902,-1140 4902,-937.17
  text "COMPONENTS MARKED 'DNP' SHOULD NOT BE POPULATED." at 1153.5,-318.5 h60
  text "ASSEMBLY VARIANT:" at 1153,-434 h60
  text ".VariantName" at 2189,-434 h60
  text "PCB VIEWED FROM TOP SIDE" at -228.5,-655.67 h60
  text "BOARD #:" at 2248,-655.67 h60
  text ".PRJ_Number" at 2793.5,-655.67 h60
  text "REV:" at 3638,-655.67 h60
  text ".PCB_Rev" at 3929.5,-655.67 h60
  text "SVN REV:" at 4476,-655.67 h60
  text ".VersionControl_RevNumber" at 4982,-655.67 h60
  text "TID #:" at 2248,-859 h60
  text ".TID" at 2793.5,-859 h60
  text "PLOT NAME =" at -228.5,-1064.34 h60
  text ".plot_File_Name" at 577,-1064.34 h60
  text "GENERATED    :" at 2250,-1064.34 h60
  text ".Print_Date" at 3119.5,-1064.34 h60
  text ".Print_Time" at 3848.5,-1064.34 h60
  text "TEXAS INSTRUMENTS" at 5113,-1064.34 h60
M6 Assembly Bottom:
  lines w10: -292.5,-727.33 6309.5,-727.33 ; -290.5,-930.67 6309.5,-930.67 ; 1115.5,-1140.5 1115.5,-937.67 ; 1737.5,-727.33 1737.5,-524 ; 2577.5,-727.33 2577.5,-524 ; 3844.5,-1134 3844.5,-524 ; 4733.5,-1134 6309,-1134 6309,-524 -292.5,-524 -292.5,-1134 2304.5,-1134 6309.5,-1134 6309.5,-524
  text "COMPONENTS MARKED 'DNP' SHOULD NOT BE POPULATED." at 6102,-318 h60
  text ".VariantName" at 5058,-434 h60
  text "ASSEMBLY VARIANT:" at 6097,-434 h60
  text ".VersionControl_RevNumber" at 1035.5,-656.17 h60
  text "SVN REV:" at 1541.5,-656.17 h60
  text ".PCB_Rev" at 2088,-656.17 h60
  text "REV:" at 2379.5,-656.17 h60
  text ".PRJ_Number" at 3224,-656.17 h60
  text "BOARD #:" at 3769.5,-656.17 h60
  text "PCB VIEWED FROM BOTTOM SIDE" at 6246,-656.17 h60
  text ".TID" at 3224,-859.5 h60
  text "TID #:" at 3769.5,-859.5 h60
  text "TEXAS INSTRUMENTS" at 904.5,-1064.84 h60
  text ".Print_Time" at 2169,-1064.84 h60
  text ".Print_Date" at 2898,-1064.84 h60
  text "GENERATED    :" at 3767.5,-1064.84 h60
  text ".plot_File_Name" at 5440.5,-1064.84 h60
  text "PLOT NAME =" at 6246,-1064.84 h60
M9 Title Sheet:
  drawing of 57 lines, arcs and shapes, not listed
  text "1" at 739.84,8036.5 h70
  text "2" at 3235.5,8036.5 h70
  text "3" at 5724.84,8036.5 h70
  text "4" at 8231.51,8036.5 h70
  text "5" at 10730.5,8036.5 h70
  text "6" at 13235.5,8036.5 h70
  text "A" at -416.5,6893.5 h70
  text "A" at 14383.5,6893.5 h70
  text "B" at -416.5,4513.5 h70
  text "B" at 14383.5,4513.5 h70
  text "C" at -416.5,2138.5 h70
  text "C" at 14383.5,2138.5 h70
  text "PROJECT TITLE:" at 11343.5,277.5 h45
  text ".PRJ_Title" at 11393.5,144.17 h70
  text "DESIGNED FOR:" at 11343.5,-23.5 h45
  text ".PRJ_Customer" at 11393.5,-163.5 h70
  text "D" at -416.5,-231.5 h70
  text "D" at 14383.5,-231.5 h70
  text "FILE NAME:" at 11343.5,-323.5 h45
  text ".PCB_File_Name_No_Path" at 11393.5,-443.5 h70
  text "Texas Instruments (TI) and/or its licensors do not warrant the accuracy or completeness of this specification" at 6374,-605.34 h45
  text "ENGINEER:" at 11343.5,-613.5 h45
  text "LAYOUT BY:" at 12848.5,-613.5 h45
  text "or any information contained therein. TI and/or its licensors do not warrant that this design will meet" at 6329.01,-718 h45
  text ".PRJ_Engineer" at 11393.5,-768.49 h70
  text ".PCB_Layout" at 12899,-768.49 h70
  text "the specifications, will be suitable for your application or fit for any particular purpose, or will operate in" at 6329.01,-830.67 h45
  text ".Layer_Name" at 577,-858.49 h60
  text "ALTIUM DESIGNER VERSION:" at 12848.5,-923.5 h45
  text "an implementation. TI and/or its licensors do not warrant that the design is production worthy. You should" at 6329.01,-943.33 h45
  text "completely validate and test your design implementation to confirm the system functionality for your application." at 6374,-1056 h45
  text ".print_Scale" at 11393.5,-1056.83 h70
  text ".Application_BuildNumber" at 12899,-1056.83 h70
  text "1" at 739.84,-1263.5 h70
  text "2" at 3235.5,-1263.5 h70
  text "3" at 5724.84,-1263.5 h70
  text "4" at 8231.51,-1263.5 h70
  text "5" at 10730.5,-1263.5 h70
  text "6" at 13235.5,-1263.5 h70
M10 Fab Notes:
  drawing of 189 lines, arcs and shapes, not listed
  text "DESIGN INFORMATION" at 12382.02,6356.17 h60
  text "MIN. TRACK WIDTH:" at 11737.46,6224.05 h60
  text "8" at 12833.7,6224.05 h60
  text "MIL" at 12988.46,6224.05 h60
  text "MIN. CLEARANCE:" at 11737.46,6099.92 h60
  text "0.2" at 12773.7,6099.93 h60
  text "mm" at 12988.46,6099.92 h60
  text "MIN. VIA PAD SIZE:" at 11737.46,5975.8 h60
  text "24" at 12803.71,5975.8 h60
  text "MIL" at 12988.46,5975.8 h60
  text "0.05mm (2MIL)" at 12432.46,5845.9 h60
  text "MINIMUM ANNULAR RING" at 11408.23,5837.67 h60
  text "EXTERNAL" at 13140.46,5837.67 h60
  text "PER" at 11608.23,5727.55 h60
  text "IPC-D-275 CLASS 2 LEVEL C" at 11828.23,5727.54 h60
  text "MIL, HOLES" at 13316.46,5627.07 h60
  text "+/-" at 12924,5618.48 h60
  text "+/-" at 13778,5618.48 h60
  text "REGISTRATION TOLERANCES:" at 11408.23,5617.42 h60
  text "METAL" at 12608,5617.42 h60
  text "5" at 13184.2,5617.42 h60
  text "3" at 14017.2,5617.42 h60
  text "MIL" at 14133.46,5617.42 h60
  text "HOLE SIZE TOLERANCE (UNLESS OTHERWISE SPECIFIED):" at 11408.23,5519.1 h60
  text "+/-" at 13778,5516.23 h60
  text "3" at 14017.2,5515.17 h60
  text "MIL" at 14133.46,5515.17 h60
  text "MATERIAL:" at 11333.46,5377.52 h60
  text "FR-4 High Tg" at 12319.9,5249 h60
  text "X" at 12175.46,5241.01 h60
  text "FR-408" at 11754.46,5236.49 h60
  text "OTHER" at 13242.46,5236.49 h60
  text "62 MIL (1.6mm) +/-10%" at 12074.56,5093.46 h60
  text "X" at 11954.46,5091.01 h60
  text "THICKNESS:" at 11408.23,5085.24 h60
  text "OTHER" at 13359.46,5085.24 h60
  text "TOLERANCE:" at 11408.23,4946.92 h60
  text "X" at 12256.46,4946.92 h60
  text "ANSI IPC-6012 TYPE 3 CLASS 2" at 12434.48,4946.92 h60
  text "OTHER +/-" at 12434.46,4802.73 h60
  text "BOW & TWIST:" at 11408.23,4657.54 h60
  text "X" at 12256.46,4657.54 h60
  text "ANSI IPC-6012 TYPE 3 CLASS 2" at 12434.48,4657.54 h60
  text "OTHER +/-" at 12434.46,4510.85 h60
  text "DRILLING:" at 11333.46,4380.23 h60
  text "NC_DRILL FILES" at 13094.46,4275.04 h60
  text "REFERENCE:" at 11408.23,4271.1 h60
  text "X" at 12065.46,4271.01 h60
  text "AS SHOWN" at 12243.46,4271.1 h60
  text "X" at 12966.46,4271.1 h60
  text "OTHER" at 13392.46,4128.85 h60
  text "PTH COPPER THICKNESS:" at 11407.91,4125.32 h60
  text "X" at 12547.14,4125.32 h60
  text "20-30 um" at 12675.14,4125.32 h60
  text "BOARD FINISH:" at 11333.46,3977.73 h60
  text "SILKSCREEN:" at 11488.68,3867.6 h60
  text "X" at 12446.46,3867.6 h60
  text "TOP" at 12563.46,3867.6 h60
  text "X" at 12956.46,3867.6 h60
  text "BOTTOM" at 13074.46,3867.6 h60
  text "SILKSCREEN COLOR:" at 11488.68,3712.41 h60
  text "X" at 12445.46,3712.41 h60
  text "WHITE" at 12563.46,3712.41 h60
  text "OTHER" at 13074.46,3712.41 h60
  text "X" at 12576.46,3568.96 h60
  text "GREEN" at 12694.46,3568.96 h60
  text "OTHER" at 13312.46,3568.96 h60
  text "SOLDER RESIST COLOR:" at 11488.68,3562.1 h60
  text "X" at 12576.46,3414.71 h60
  text "MATTE" at 12694.46,3414.71 h60
  text "SEMI-GLOSS" at 13312,3414.07 h60
  text "IMMERSION GOLD (ENIG)" at 12394.46,3241.94 h60
  text "ENEPIG" at 13732,3234.72 h60
  text "SURFACE FINISH:" at 11333.46,3233.72 h60
  text "X" at 12216.46,3233.72 h60
  text "IMM. TIN/SILVER OR EQUIV" at 11663,3096.4 h60
  text "OTHER" at 13094.46,3092.47 h60
  text "ARRAY/PANEL:" at 11333.46,2937.09 h60
  text "CUT AND TRIM PER M1 BOARD OUTLINE" at 12394.46,2928.87 h60
  text "N.C. ROUTE" at 12394.46,2792.9 h60
  text "X" at 13082.46,2792.9 h60
  text "V. SCORE" at 13260.46,2792.9 h60
  text "CERTIFICATION:" at 11333.46,2663.77 h60
  text "MATERIALS AND WORKMANSHIP FOR ALL PCBS" at 12058.46,2663.77 h60
  text "TO MEET OR EXCEED THE REQUIREMENTS OF:" at 12058.46,2569.71 h60
  text "X" at 11695.97,2441.08 h60
  text "ANSI IPC-A-600F CLASS ->" at 11823.96,2441.08 h60
  text "X" at 13471.97,2441.08 h60
  text "2" at 13581.96,2441.08 h60
  text "1" at 13266.96,2439.58 h60
  text "3" at 13935.96,2439.58 h60
  text "X" at 12507.97,2293.39 h60
  text "RoHS" at 12635.96,2293.39 h60
  text "OTHER" at 13280.36,2293.39 h60
  text "PER ORDER" at 13677.42,2293.39 h60
  text "ALL BOARDS MUST MEET OR EXCEED UL94-V0 REQUIREMENTS." at 11361,2139.57 h60
  text "PCB MUST BEAR THE UL94V-0 UL REGISTERED MATERIAL ID NUMBER" at 11361,2023.5 h60
  text "ADDITIONAL REQUIREMENTS:" at 11333.46,1854.08 h60
  text "MICROSECTION:" at 11408.23,1746.95 h60
  text "YES" at 12313.96,1746.95 h60
  text "REQUIRED" at 13175.46,1602.62 h60
  text "BARE BOARD ELEC. TEST:" at 11408.23,1599.76 h60
  text "NONE" at 12713.96,1599.76 h60
  text "X" at 13057.46,1599.76 h60
  text "PER ORDER" at 13767.46,1599.76 h60
  text "XX MIL VIAS REQUIRE NON-CONDUCTIVE FILL AND PLANARIZE" at 11576.38,1394.82 h59
  text "XX MIL VIAS REQUIRE CONDUCTIVE FILL AND PLANARIZE" at 11584.38,1290.84 h60
  text "OUTER XX MIL TRACES REQUIRE 50 OHM SINGLE-ENDED IMPEDANCE" at 11583.39,1127.46 h58
  text "LAYER 2 & 3 (INNER LAYERS) XX MIL WIDE, XX MIL SPACE / TRACES REQUIRE 100 OHM DIFFERENTIAL IMPEDANCE" at 11575.39,891.74 h60
  text ".Layer_Name" at 577,-858.49 h60
M11 Gerber Information:
  lines w10: -292,-930.17 6308,-930.17 ; -292,-726.83 6310,-726.83 ; -292,-523.5 -292,-1133.5 3713,-1133.5 6310,-1133.5 6310,-523.5 -291.5,-523.5 -291.5,-1133.5 1284,-1133.5 ; 2173,-1133.5 2173,-523.5 ; 3440,-726.83 3440,-523.5 ; 4280,-726.83 4280,-523.5 ; 4902,-1140 4902,-937.17
  text "ALL ARTWORK VIEWED FROM TOP SIDE" at -228.5,-655.67 h60
  text "BOARD #:" at 2248,-655.67 h60
  text ".PRJ_Number" at 2793.5,-655.67 h60
  text "REV:" at 3638,-655.67 h60
  text ".PCB_Rev" at 3929.5,-655.67 h60
  text "SVN REV:" at 4476,-655.67 h60
  text ".VersionControl_RevNumber" at 4982,-655.67 h60
  text "LAYER NAME =" at -228.5,-858.49 h60
  text "TID #:" at 2248,-859 h60
  text ".TID" at 2793.5,-859 h60
  text "PLOT NAME =" at -228.5,-1064.34 h60
  text ".plot_File_Name" at 577,-1064.34 h60
  text "GENERATED    :" at 2250,-1064.34 h60
  text ".Print_Date" at 3119.5,-1064.34 h60
  text ".Print_Time" at 3848.5,-1064.34 h60
  text "TEXAS INSTRUMENTS" at 5113,-1064.34 h60
M12 Stackup:
  drawing of 295 lines, arcs and shapes, not listed
  text "Layer" at 6679.32,7132.54 h60
  text "Name" at 7089.23,7132.54 h60
  text "Material" at 8028.97,7132.54 h60
  text "Thickness" at 8888.74,7132.54 h60
  text "Constant" at 9538.58,7132.54 h60
  text "Board Layer Stack" at 10108.44,7132.54 h60
  text "1" at 6679.32,7012.54 h60
  text "Top Overlay" at 7089.23,7012.54 h60
  text "2" at 6679.32,6892.54 h60
  text "Top Solder" at 7089.23,6892.54 h60
  text "Solder Resist" at 8028.97,6892.54 h60
  text "0.40mil" at 8888.74,6892.54 h60
  text "3.5" at 9538.58,6892.54 h60
  text "3" at 6679.32,6772.54 h60
  text "Top Layer" at 7089.23,6772.54 h60
  text "Copper" at 8028.97,6772.54 h60
  text "2.80mil" at 8888.74,6772.54 h60
  text "4" at 6679.32,6652.54 h60
  text "Dielectric 1" at 7089.23,6652.54 h60
  text "FR-4" at 8028.97,6652.54 h60
  text "15.00mil" at 8888.74,6652.54 h60
  text "4.8" at 9538.58,6652.54 h60
  text "5" at 6679.32,6532.54 h60
  text "Signal Layer 1" at 7089.23,6532.54 h60
  text "Copper" at 8028.97,6532.54 h60
  text "2.80mil" at 8888.74,6532.54 h60
  text "6" at 6679.32,6412.54 h60
  text "Dielectric 2" at 7089.23,6412.54 h60
  text "FR-4" at 8028.97,6412.54 h60
  text "20.00mil" at 8888.74,6412.54 h60
  text "4.2" at 9538.58,6412.54 h60
  text "7" at 6679.32,6292.54 h60
  text "Signal Layer 2" at 7089.23,6292.54 h60
  text "Copper" at 8028.97,6292.54 h60
  text "2.80mil" at 8888.74,6292.54 h60
  text "8" at 6679.32,6172.54 h60
  text "Dielectric 3" at 7089.23,6172.54 h60
  text "FR-4" at 8028.97,6172.54 h60
  text "15.00mil" at 8888.74,6172.54 h60
  text "4.2" at 9538.58,6172.54 h60
  text "9" at 6679.32,6052.54 h60
  text "Bottom Layer" at 7089.23,6052.54 h60
  text "Copper" at 8028.97,6052.54 h60
  text "2.80mil" at 8888.74,6052.54 h60
  text "10" at 6679.32,5932.54 h60
  text "Bottom Solder" at 7089.23,5932.54 h60
  text "Solder Resist" at 8028.97,5932.54 h60
  text "0.40mil" at 8888.74,5932.54 h60
  text "3.5" at 9538.58,5932.54 h60
  text "11" at 6679.32,5812.54 h60
  text "Bottom Overlay" at 7089.23,5812.54 h60
  text ".Layer_Name" at 577,-858.49 h60
M13 Component Bodies Top:
  text ".Layer_Name" at 577,-858.49 h60
M14 Component Bodies Bottom:
  text ".Layer_Name" at 577,-858.49 h60
M15 Courtyards Top:
  text ".Layer_Name" at 577,-858.49 h60
M16 Courtyards Bottom:
  text ".Layer_Name" at 577,-858.49 h60
Drill Drawing:
  drawing of 181 lines, arcs and shapes, not listed
  text "Symbol" at 6384.72,2846.87 h70.95
  text "Quantity" at 6680.81,2846.87 h70.95
  text "Finished Hole Size" at 7007.87,2846.87 h70.95
  text "Plated" at 7634.92,2846.87 h70.95
  text "Hole Type" at 7890.22,2846.87 h70.95
  text "Drill Layer Pair" at 8259.79,2846.87 h70.95
  text "Hole Tolerance" at 8973.68,2846.87 h70.95
  text "13" at 6680.81,2724.34 h59.12
  text "7.87mil (0.200mm)" at 7007.87,2724.34 h59.12
  text "PTH" at 7634.92,2724.34 h59.12
  text "Round" at 7890.22,2724.34 h59.12
  text "Top Layer - Bottom Layer" at 8259.79,2724.34 h59.12
  text "4" at 6680.81,2601.81 h59.12
  text "8.00mil (0.203mm)" at 7007.87,2601.81 h59.12
  text "PTH" at 7634.92,2601.81 h59.12
  text "Round" at 7890.22,2601.81 h59.12
  text "Top Layer - Bottom Layer" at 8259.79,2601.81 h59.12
  text "15" at 6680.81,2479.29 h59.12
  text "10.00mil (0.254mm)" at 7007.87,2479.29 h59.12
  text "PTH" at 7634.92,2479.29 h59.12
  text "Round" at 7890.22,2479.29 h59.12
  text "Top Layer - Bottom Layer" at 8259.79,2479.29 h59.12
  text "12" at 6680.81,2356.76 h59.12
  text "12.00mil (0.305mm)" at 7007.87,2356.76 h59.12
  text "PTH" at 7634.92,2356.76 h59.12
  text "Round" at 7890.22,2356.76 h59.12
  text "Top Layer - Bottom Layer" at 8259.79,2356.76 h59.12
  text "167" at 6680.81,2234.23 h59.12
  text "20.00mil (0.508mm)" at 7007.87,2234.23 h59.12
  text "PTH" at 7634.92,2234.23 h59.12
  text "Round" at 7890.22,2234.23 h59.12
  text "Top Layer - Bottom Layer" at 8259.79,2234.23 h59.12
  text "16" at 6680.81,2111.7 h59.12
  text "35.04mil (0.890mm)" at 7007.87,2111.7 h59.12
  text "PTH" at 7634.92,2111.7 h59.12
  text "Round" at 7890.22,2111.7 h59.12
  text "Top Layer - Bottom Layer" at 8259.79,2111.7 h59.12
  text "15" at 6680.81,1989.17 h59.12
  text "39.37mil (1.000mm)" at 7007.87,1989.17 h59.12
  text "PTH" at 7634.92,1989.17 h59.12
  text "Round" at 7890.22,1989.17 h59.12
  text "Top Layer - Bottom Layer" at 8259.79,1989.17 h59.12
  text "45" at 6680.81,1866.65 h59.12
  text "40.00mil (1.016mm)" at 7007.87,1866.65 h59.12
  text "PTH" at 7634.92,1866.65 h59.12
  text "Round" at 7890.22,1866.65 h59.12
  text "Top Layer - Bottom Layer" at 8259.79,1866.65 h59.12
  text "2" at 6680.81,1744.12 h59.12
  text "43.31mil (1.100mm)" at 7007.87,1744.12 h59.12
  text "PTH" at 7634.92,1744.12 h59.12
  text "Round" at 7890.22,1744.12 h59.12
  text "Top Layer - Bottom Layer" at 8259.79,1744.12 h59.12
  text "2" at 6680.81,1621.59 h59.12
  text "50.00mil (1.270mm)" at 7007.87,1621.59 h59.12
  text "PTH" at 7634.92,1621.59 h59.12
  text "Round" at 7890.22,1621.59 h59.12
  text "Top Layer - Bottom Layer" at 8259.79,1621.59 h59.12
  text "4" at 6680.81,1499.06 h59.12
  text "61.81mil (1.570mm)" at 7007.87,1499.06 h59.12
  text "PTH" at 7634.92,1499.06 h59.12
  text "Round" at 7890.22,1499.06 h59.12
  text "Top Layer - Bottom Layer" at 8259.79,1499.06 h59.12
  text "5" at 6680.81,1376.53 h59.12
  text "63.00mil (1.600mm)" at 7007.87,1376.53 h59.12
  text "PTH" at 7634.92,1376.53 h59.12
  text "Round" at 7890.22,1376.53 h59.12
  text "Top Layer - Bottom Layer" at 8259.79,1376.53 h59.12
  text "4" at 6680.81,1254.01 h59.12
  text "128.00mil (3.251mm)" at 7007.87,1254.01 h59.12
  text "PTH" at 7634.92,1254.01 h59.12
  text "Round" at 7890.22,1254.01 h59.12
  text "Top Layer - Bottom Layer" at 8259.79,1254.01 h59.12
  text "304 Total" at 6680.81,1131.48 h59.12
  text ".Layer_Name" at 577,-858.49 h60
Mechanical 17:
  text ".Layer_Name" at 577,-858.49 h60
Mechanical 18:
  text ".Layer_Name" at 577,-858.49 h60
Mechanical 19:
  text ".Layer_Name" at 577,-858.49 h60

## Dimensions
0,-400 to 1000,-400 on M2 Board Dimensions
0,0 to 5629.06,19.68 on M2 Board Dimensions
0,0 to -16.35,3732 on M2 Board Dimensions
